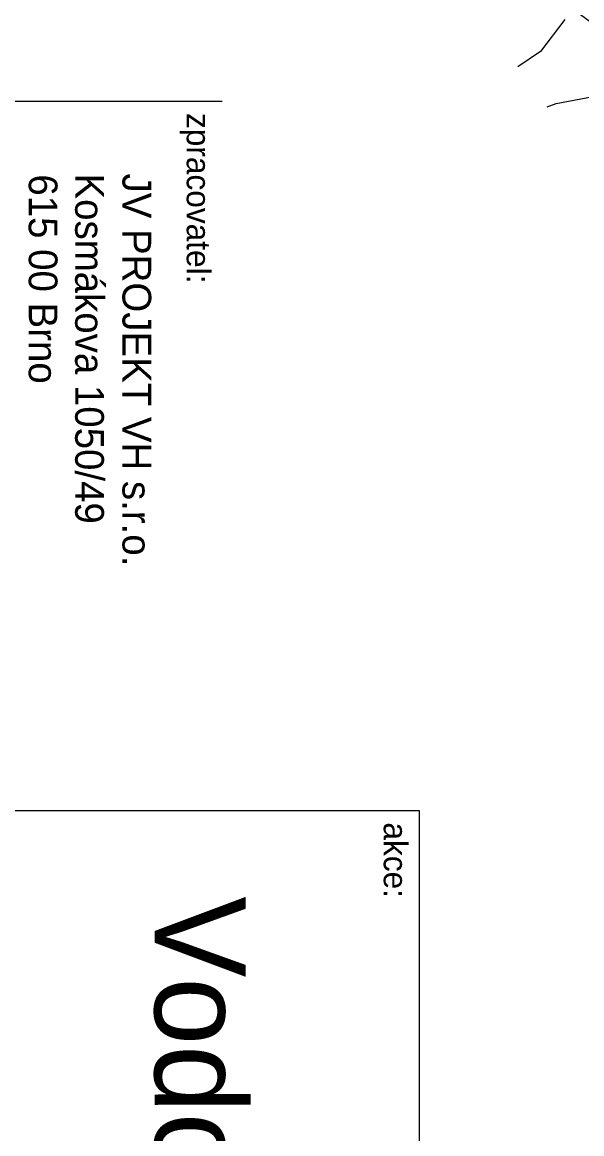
# Model space of a CAD drawing. Extents: x -510989 to -501240, y -1184665 to -1176089.
# Drawn here: x -506025 to -505552, y -1183393 to -1182453 of the extents above; entities that cross this region are included whole.
import ezdxf

# ---------------------------------------------------------------- set-up
doc = ezdxf.new("R2010")
doc.units = 0
for name, color, linetype in [('Implicitní', 7, 'Continuous'), ('NAVRH_rozvodnice', 7, 'Continuous'), ('rozpiska', 7, 'Continuous'), ('STAV_povodi', 7, 'Continuous'), ('vrstevnice_01', 7, 'Continuous'), ('vrstevnice_02', 7, 'Continuous')]:
    doc.layers.add(name, color=color, linetype=linetype)

# ---------------------------------------------------------------- blocks, each defined once
blk = doc.blocks.new('rozpiska-cary')
at = {"layer": 'Implicitní'}
for p, q in [((-0.12, -0.102), (-0.12, -0.037)), ((-0.12, -0.037), (0, -0.037)), ((-0.18, -0.082), (-0.18, -0.053655))]:
    blk.add_line(p, q, dxfattribs=at)

msp = doc.modelspace()

# ---------------------------------------------------------------- linework, layer by layer
at = {"layer": 'NAVRH_rozvodnice'}
msp.add_arc((-505722.83, -1182688.68), 295.41, 40.4572, 56.97669, dxfattribs=at)
at = {"layer": 'STAV_povodi'}
msp.add_arc((-505722.83, -1182688.68), 295.41, 40.4572, 56.97669, dxfattribs=at)
at = {"layer": 'vrstevnice_01'}
msp.add_lwpolyline([(-505581.18, -1182524.79), (-505573.59, -1182522), (-505515.5, -1182511), (-505507.19, -1182506), (-505499.81, -1182500), (-505496.31, -1182494), (-505494.91, -1182490), (-505492.81, -1182478), (-505493.69, -1182468), (-505499, -1182446)], dxfattribs=at)
at = {"layer": 'vrstevnice_02'}
for points in [[(-505566.19, -1182451), (-505586.81, -1182478)], [(-505586.81, -1182478), (-505606.04, -1182490.97)]]:
    msp.add_lwpolyline(points, dxfattribs=at)

# ---------------------------------------------------------------- block references
at = {"layer": 'rozpiska', "xscale": 10000, "yscale": 10000, "rotation": -90.00000000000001}
msp.add_blockref('rozpiska-cary', (-505319.31, -1184320), dxfattribs=at)

# ---------------------------------------------------------------- texts
at = {"layer": 'rozpiska'}
for s, height, p in [('zpracovatel:', 20, (-505885.86, -1182530)), ('JV PROJEKT VH s.r.o.', 24.3, (-505940.16, -1182581.22)), ('615 00 Brno', 24.3, (-506019.4, -1182581.94)), ('Kosmákova 1050/49', 24.3, (-505980.14, -1182581.22)), ('akce:', 20, (-505719.31, -1183130)), ('Vodohospodářské posouzení', 77, (-505912.94, -1183192.44))]:
    msp.add_text(s, height=height, rotation=270, dxfattribs=at).set_placement(p)

doc.saveas('drawing.dxf')
